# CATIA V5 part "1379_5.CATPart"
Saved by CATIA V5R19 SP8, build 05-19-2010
Part number: 5
Bounding box of the stored display mesh (mm): x -5 to 5, y 10.5 to 60.5, z -8.5 to 10
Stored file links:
  C:\Users\ThinkMotion\Desktop\EU_thinkMotion\iao\IAO_MMS_Groupe3\bblot\bblot\1379_5.CATPart
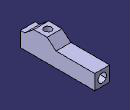
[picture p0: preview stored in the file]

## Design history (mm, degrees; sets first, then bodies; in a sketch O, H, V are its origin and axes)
Body1 (main body)
  Line1: stored without definition
  Point1: stored without definition
  Point2: stored without definition
  Sketch1 on yz-plane, origin (0, 0, 0), H (0, 1, 0), V (0, 0, 1)
    line L1 (10.5, 5) -> (10.5, -5)
    line L2 (10.5, -5) -> (60.5, -5)
    line L3 (60.5, -5) -> (60.5, 5)
    line L4 (60.5, 5) -> (34.5, 5)
    line L5 (34.5, 5) -> (28.5, 10)
    line L6 (28.5, 10) -> (19.5, 10)
    line L7 (19.5, 10) -> (13.5, 5)
    point P8 (13.5, 5)
    line L8 (13.5, 5) -> (10.5, 5)
    construction line L9 (60.5, 0) -> (10.5, 0)
    point P9 (60.5, 0)
    point P10 (10.5, 0)
    reference projected line E1 through (0, 0) direction (1, 0) from Line1
    construction line L10 (24, 10) -> (24, 5)
    point P11 (24, 10)
    point P12 (24, 5)
    reference projected point E2 (24, 9) from Point1
    reference projected point E3 (24, 9) from Point2
    construction line L11 (19.5, 10) -> (24, 13.75)
    point P13 (24, 13.75)
    axis line L12 (28.5, 10) -> (24, 13.75)
    length L3 = 10
    length L6 = 9
    length L2 = 50
    length L8 = 3
    length L4 = 26
    distance E3 L6 = 1
    vertical: L1 V, L3 V, L10 V
    horizontal: L2 H, L4 H, L6 H, L8 H, L9 H
    coincidence: P8 L4, P9 L3, P10 L1, L9 E1, P11 L6, P12 L4, L10 E2, P13 L7, P13 L5, L10 P13
    midpoint: P9 L3, P11 L6
  Pad1: profile Sketch1, direction (1, 0, 0), length 5, opposite side length 5
  Sketch2 on face of Pad1 from Sketch1.L3, origin (-1.2101, 60.5, 1.2101), H (1, 0, 0), V (0, 0, -1)
    point P1 (1.2101, 1.2101)
    reference projected point E1 (1.2101, 1.2101) from Line4
    coincidence: P1 E1
  Hole1: placed by Sketch2, at (0, 60.5, 0) direction (0, -1, 0), diameter 6, through (limit type 6), offset -3
  Sketch3 on face of Pad1 from Sketch1.L6, origin (0.1468, 23.2882, 10), H (1, 0, 0), V (0, 1, 0)
    point P1 (-0.1468, 0.7118)
    reference projected point E1 (-0.1468, 0.7118) from Point4
    coincidence: P1 E1
  Hole2: placed by Sketch3, at (0, 24, 10) direction (0, 0, -1), diameter 5, depth 5
  Sketch4 on face of Pad1 from Sketch1.L1, origin (-0.1459, 10.5, -1.8229), H (1, 0, 0), V (0, 0, 1)
    point P1 (0.1459, 1.8229)
    reference projected point E1 (0.1459, 1.8229) from Line5
    coincidence: P1 E1
  Hole3: placed by Sketch4, at (0, 10.5, 0) direction (0, 1, 0), diameter 4, through (limit type 6)
  Line2: stored without definition
  Sketch5 on face of Pad1 from Sketch1.L2, origin (0, 0, -5), H (1, 0, 0), V (0, -1, 0)
    line L1 (-1, -22.5) -> (1, -22.5)
    line L2 (1, -22.5) -> (1, -37.5)
    line L3 (1, -37.5) -> (-1, -37.5)
    line L4 (-1, -37.5) -> (-1, -22.5)
    axis line L5 (0, -22.5) -> (0, -37.5)
    point P5 (0, -22.5)
    point P6 (0, -37.5)
    reference projected line E1 through (0, 0) direction (0, -1) from Line2
    reference projected line E2 (-5, -10.5) -> (5, -10.5) from edge [face of Pad1 from Sketch1.L2 | face of Pad1 from Sketch1.L1]
    length L1 = 2
    distance L1 E2 = 12
    length L4 = 15
    horizontal: L1 H, L3 H
    vertical: L2 V, L4 V, L5 V
    coincidence: P5 L1, P6 L3, L5 E1
    midpoint: P5 L1
  Pocket1: profile Sketch5, direction (0, 0, 1), through (limit type 6)
  Sketch6 on face of Pocket1 from Sketch5.L4, origin (-1, 0, 0), H (0, 1, 0), V (0, 0, 1)
    line L1 (11.5, -7) -> (11.5, -5)
    line L2 (11.5, -5) -> (17.1213, -5)
    line L3 (17.1213, -5) -> (14.0607, -8.0607)
    arc A1 centre (13, -7) radius 1.5 from (14.0607, -8.0607) to (11.5, -7) cw
    point P5 (13, -7)
    reference projected line E1 (8, -5) -> (58, -5) from edge [face of Pad1 from Sketch1.L2 | end face of Pad1]
    circle A2 centre (13, -7) radius 1
    reference projected point E2 (13, -7) from Point6
    reference projected line E3 (10.5, 5) -> (10.5, -5) from edge [face of Pad1 from Sketch1.L1 | end face of Pad1]
    radius A2 = 1
    angle L2 L3 = 45
    distance E3 L1 = 1
    vertical: L1 V
    horizontal: L2 H
    tangency: A1 L3, A1 L1
    coincidence: L2 E1, P5 E2
  Pad2: profile Sketch6, direction (-1, 0, 0), length 1
  Point3: type Center, Curve edge [face of Pad1 from Sketch1.L6 | face of Hole2]
  Line3: type Normal, RefPoint Point3, RefSkin face of Pad1 from Sketch1.L6, Start 0, End 20
  Line4: stored without definition
  Point4: stored without definition
  Line5: stored without definition
  Point5: stored without definition
  Point6: stored without definition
